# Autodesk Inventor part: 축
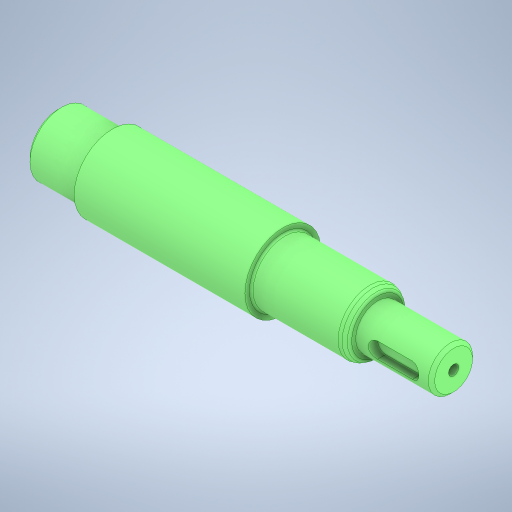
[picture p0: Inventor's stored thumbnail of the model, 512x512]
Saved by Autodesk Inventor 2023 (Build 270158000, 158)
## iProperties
Created: 2026-07
Part Number: 축
Material: 강철, 탄소
Document SubType Name: Modeling
Designer: home
Density: 7.85 g/cm^3
Appearance: 기본값
Author: jhkim
Sending System: Autodesk Inventor 2027
Preprocessor: ST-DEVELOPER v20.1
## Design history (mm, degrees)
feature "솔리드1"
node "솔리드2"
